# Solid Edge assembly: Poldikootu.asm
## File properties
Author: Türk
Template: Iso Assembly.asm
Last saved by: Türk
Revision: 3
Application: Solid Edge
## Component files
Mutter.par
Polt80x20.par
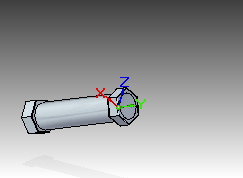
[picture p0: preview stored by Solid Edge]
